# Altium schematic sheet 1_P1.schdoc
size 309 x 223 mm; Symbol: Sheet-Symbol_A4; Device: Sheet-Symbol_A4; Company: LuXeria; Drawed: Peanut; Reviewed: EasyEDA Pro; Version: V0.2; Page Size: A4; @Project Name: LuxBadge; @Page Count: 1; @Update Date: 2023-06-16; @Create Date: 2023-06-14; @Schematic Name: LuxBadge; Part Number: JLCPCB-002; @Page No: 1; @Page Name: P1
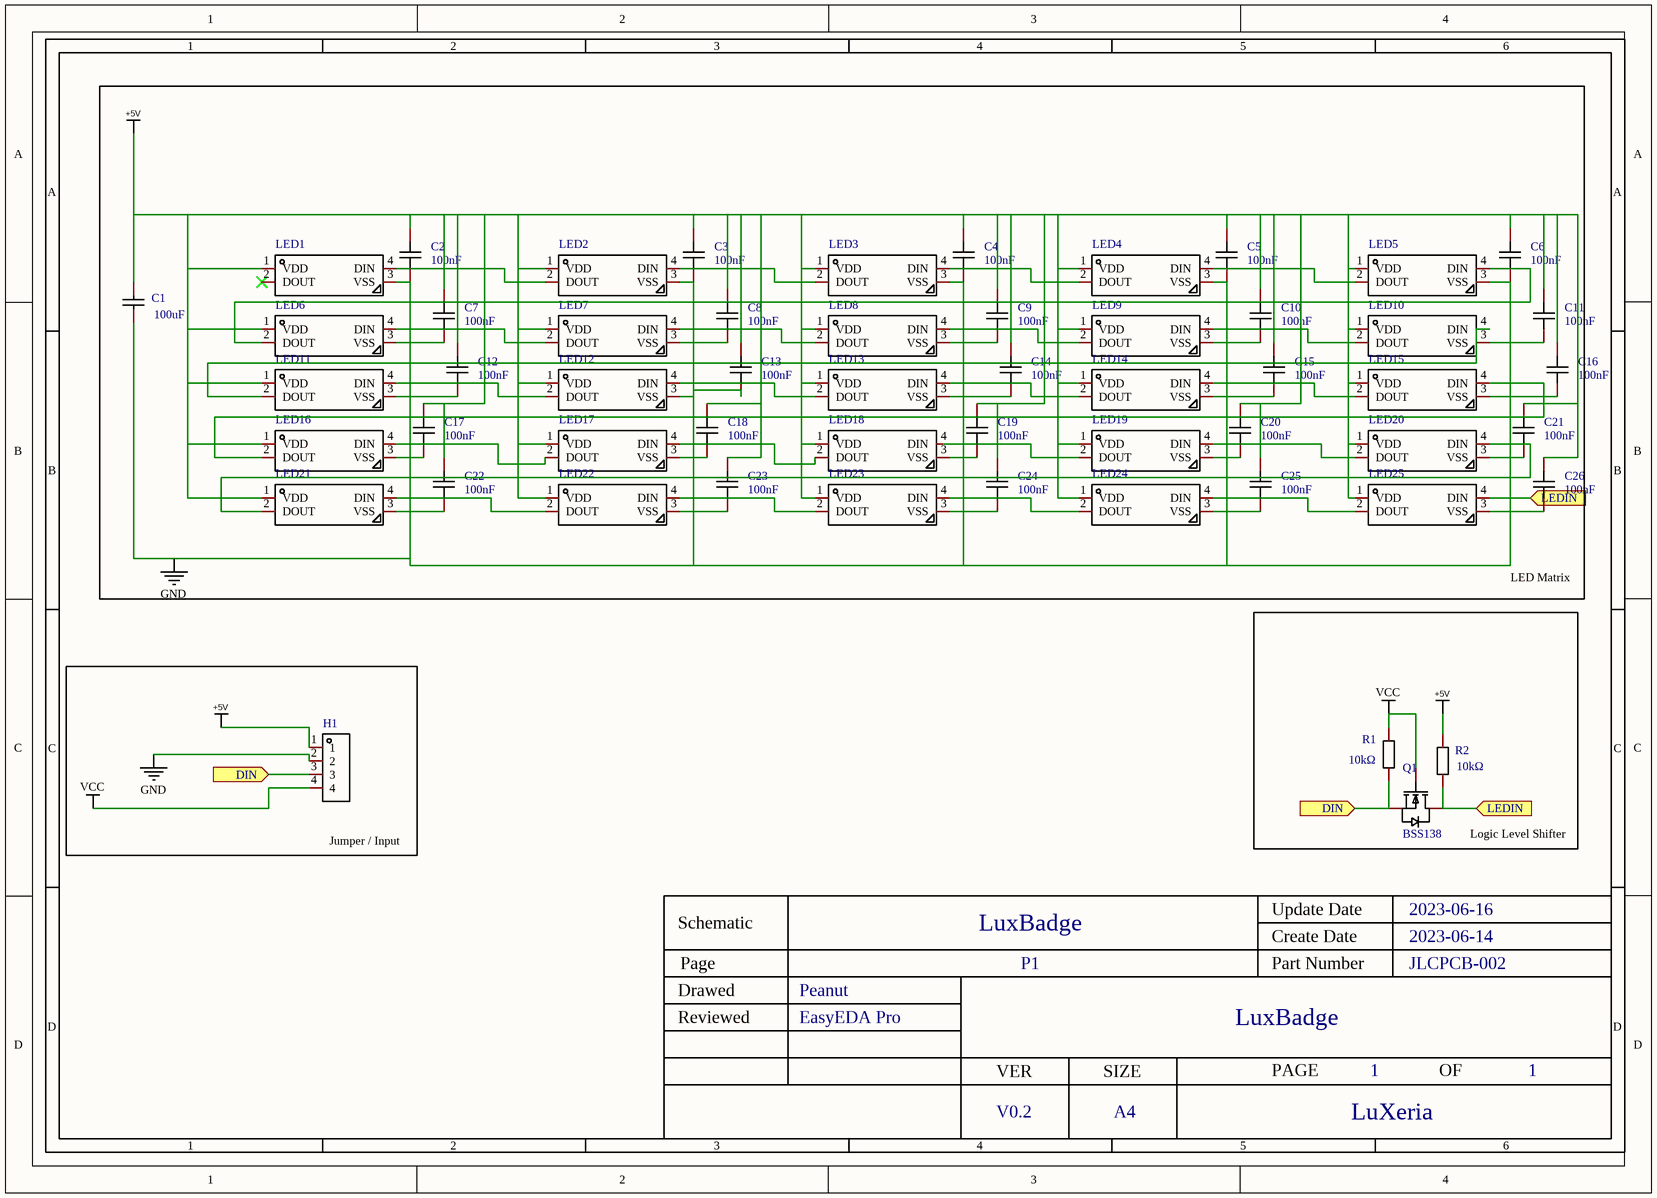
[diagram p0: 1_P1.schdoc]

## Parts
C1  100uF  [C1206]
C2  100nF  [C0402]
C3  100nF  [C0402]
C4  100nF  [C0402]
C5  100nF  [C0402]
C6  100nF  [C0402]
C7  100nF  [C0402]
C8  100nF  [C0402]
C9  100nF  [C0402]
C10  100nF  [C0402]
C11  100nF  [C0402]
C12  100nF  [C0402]
C13  100nF  [C0402]
C14  100nF  [C0402]
C15  100nF  [C0402]
C16  100nF  [C0402]
C17  100nF  [C0402]
C18  100nF  [C0402]
C19  100nF  [C0402]
C20  100nF  [C0402]
C21  100nF  [C0402]
C22  100nF  [C0402]
C23  100nF  [C0402]
C24  100nF  [C0402]
C25  100nF  [C0402]
C26  100nF  [C0402]
H1  2.54-1*4P母  [HDR-TH_4P-P2.54-V-F]  (value not drawn)
LED1  WS2812C/W  [LED-SMD_4P-L5.0-W5.0-TL_WS2812B-B]  (value not drawn)
LED2  WS2812C/W  [LED-SMD_4P-L5.0-W5.0-TL_WS2812B-B]  (value not drawn)
LED3  WS2812C/W  [LED-SMD_4P-L5.0-W5.0-TL_WS2812B-B]  (value not drawn)
LED4  WS2812C/W  [LED-SMD_4P-L5.0-W5.0-TL_WS2812B-B]  (value not drawn)
LED5  WS2812C/W  [LED-SMD_4P-L5.0-W5.0-TL_WS2812B-B]  (value not drawn)
LED6  WS2812C/W  [LED-SMD_4P-L5.0-W5.0-TL_WS2812B-B]  (value not drawn)
LED7  WS2812C/W  [LED-SMD_4P-L5.0-W5.0-TL_WS2812B-B]  (value not drawn)
LED8  WS2812C/W  [LED-SMD_4P-L5.0-W5.0-TL_WS2812B-B]  (value not drawn)
LED9  WS2812C/W  [LED-SMD_4P-L5.0-W5.0-TL_WS2812B-B]  (value not drawn)
LED10  WS2812C/W  [LED-SMD_4P-L5.0-W5.0-TL_WS2812B-B]  (value not drawn)
LED11  WS2812C/W  [LED-SMD_4P-L5.0-W5.0-TL_WS2812B-B]  (value not drawn)
LED12  WS2812C/W  [LED-SMD_4P-L5.0-W5.0-TL_WS2812B-B]  (value not drawn)
LED13  WS2812C/W  [LED-SMD_4P-L5.0-W5.0-TL_WS2812B-B]  (value not drawn)
LED14  WS2812C/W  [LED-SMD_4P-L5.0-W5.0-TL_WS2812B-B]  (value not drawn)
LED15  WS2812C/W  [LED-SMD_4P-L5.0-W5.0-TL_WS2812B-B]  (value not drawn)
LED16  WS2812C/W  [LED-SMD_4P-L5.0-W5.0-TL_WS2812B-B]  (value not drawn)
LED17  WS2812C/W  [LED-SMD_4P-L5.0-W5.0-TL_WS2812B-B]  (value not drawn)
LED18  WS2812C/W  [LED-SMD_4P-L5.0-W5.0-TL_WS2812B-B]  (value not drawn)
LED19  WS2812C/W  [LED-SMD_4P-L5.0-W5.0-TL_WS2812B-B]  (value not drawn)
LED20  WS2812C/W  [LED-SMD_4P-L5.0-W5.0-TL_WS2812B-B]  (value not drawn)
LED21  WS2812C/W  [LED-SMD_4P-L5.0-W5.0-TL_WS2812B-B]  (value not drawn)
LED22  WS2812C/W  [LED-SMD_4P-L5.0-W5.0-TL_WS2812B-B]  (value not drawn)
LED23  WS2812C/W  [LED-SMD_4P-L5.0-W5.0-TL_WS2812B-B]  (value not drawn)
LED24  WS2812C/W  [LED-SMD_4P-L5.0-W5.0-TL_WS2812B-B]  (value not drawn)
LED25  WS2812C/W  [LED-SMD_4P-L5.0-W5.0-TL_WS2812B-B]  (value not drawn)
Q1  BSS138  [SOT-23-3_L2.9-W1.3-P1.90-LS2.4-BR]
R1  10kΩ  [R0805]
R2  10kΩ  [R0805]

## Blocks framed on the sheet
LED Matrix: C1-C26 LED1-LED25
Logic Level Shifter: Q1 R1 R2
Jumper / Input: H1

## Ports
DIN (in), LEDIN (in)

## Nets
+5V: C1.2 C2.2 C3.2 C4.2 C5.2 C6.2 C7.2 C8.2 C9.2 C10.2 C11.2 C12.2 C13.2 C14.2 C15.2 C16.2 C17.2 C18.2 C19.2 C20.2 C21.2 C22.2 C23.2 C24.2 C25.2 C26.2 H1.1 LED1.1(VDD) LED2.1(VDD) LED3.1(VDD) LED4.1(VDD) LED5.1(VDD) LED6.1(VDD) LED7.1(VDD) LED8.1(VDD) LED9.1(VDD) LED10.1(VDD) LED11.1(VDD) LED12.1(VDD) LED13.1(VDD) LED14.1(VDD) LED15.1(VDD) LED16.1(VDD) LED17.1(VDD) LED18.1(VDD) LED19.1(VDD) LED20.1(VDD) LED21.1(VDD) LED22.1(VDD) LED23.1(VDD) LED24.1(VDD) LED25.1(VDD) R2.2
GND: C1.1 C2.1 C3.1 C4.1 C5.1 C6.1 C7.1 C8.1 C9.1 C10.1 C11.1 C12.1 C13.1 C14.1 C15.1 C16.1 C17.1 C18.1 C19.1 C20.1 C21.1 C22.1 C23.1 C24.1 C25.1 C26.1 H1.2 LED1.3(VSS) LED2.3(VSS) LED3.3(VSS) LED4.3(VSS) LED5.3(VSS) LED6.3(VSS) LED7.3(VSS) LED8.3(VSS) LED9.3(VSS) LED10.3(VSS) LED11.3(VSS) LED12.3(VSS) LED13.3(VSS) LED14.3(VSS) LED15.3(VSS) LED16.3(VSS) LED17.3(VSS) LED18.3(VSS) LED19.3(VSS) LED20.3(VSS) LED21.3(VSS) LED22.3(VSS) LED23.3(VSS) LED24.3(VSS) LED25.3(VSS)
VCC: H1.4 Q1.1(G) R1.2
DIN: H1.3 Q1.2(S) R1.1 ; port DIN
LEDIN: LED25.4(DIN) Q1.3(D) R2.1 ; port LEDIN
NetLED1_4: LED1.4(DIN) LED2.2(DOUT)
NetLED2_4: LED2.4(DIN) LED3.2(DOUT)
NetLED3_4: LED3.4(DIN) LED4.2(DOUT)
NetLED4_4: LED4.4(DIN) LED5.2(DOUT)
NetLED5_4: LED5.4(DIN) LED6.2(DOUT)
NetLED6_4: LED6.4(DIN) LED7.2(DOUT)
NetLED7_4: LED7.4(DIN) LED8.2(DOUT)
NetLED8_4: LED8.4(DIN) LED9.2(DOUT)
NetLED9_4: LED9.4(DIN) LED10.2(DOUT)
NetLED10_4: LED10.4(DIN) LED11.2(DOUT)
NetLED11_4: LED11.4(DIN) LED12.2(DOUT)
NetLED12_4: LED12.4(DIN) LED13.2(DOUT)
NetLED13_4: LED13.4(DIN) LED14.2(DOUT)
NetLED14_4: LED14.4(DIN) LED15.2(DOUT)
NetLED15_4: LED15.4(DIN) LED16.2(DOUT)
NetLED16_4: LED16.4(DIN) LED17.2(DOUT)
NetLED17_4: LED17.4(DIN) LED18.2(DOUT)
NetLED18_4: LED18.4(DIN) LED19.2(DOUT)
NetLED19_4: LED19.4(DIN) LED20.2(DOUT)
NetLED20_4: LED20.4(DIN) LED21.2(DOUT)
NetLED21_4: LED21.4(DIN) LED22.2(DOUT)
NetLED22_4: LED22.4(DIN) LED23.2(DOUT)
NetLED23_4: LED23.4(DIN) LED24.2(DOUT)
NetLED24_4: LED24.4(DIN) LED25.2(DOUT)

Not connected (* = marked no-connect by the designer): LED1 2(DOUT)*

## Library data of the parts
C1 = CL31A107MQHNNNE: Capacitance: Tolerance:±20% Tolerance:±20% Voltage Rated: Temperature Coefficient:; Manufacturer: SAMSUNG(三星); Add into BOM: yes; Tolerance: ±20%
C2-C26 = CC0402KRX7R5BB104: Capacitance: Tolerance:±10% Tolerance:±10% Voltage Rated: Temperature Coefficient:; Manufacturer: YAGEO(国巨); Add into BOM: yes; Tolerance: ±10%
H1 = 2.54-1*4P母: Number of Rows:单排 Number of Holes:4 Pitch:2.54mm Holes Structure:1x4P Row Spacing:- Mounting Type:Straight Circular Hole / Square Hole:Square Holes Current Rating (Max):3A Voltage Rating (Max):- Holes Direction:Top Insulation Height:- Contact Material:bro; Manufacturer: BOOMELE(博穆精密); Add into BOM: no; Convert to PCB: yes; Number of Holes: 4; Pitch: 2.54mm; Holes Structure: 1x4P; Current Rating (Max): 3A; Holes Direction: Top
LED1-LED25 = WS2812C/W: Emitted Color:RGB Diode Configuration:- Lens Color:- Dominant Wavelength:465nm~475nm；620nm~625nm；515nm~525nm Dominant Wavelength:465nm~475nm；620nm~625nm；515nm~525nm Peak Wavelength:- Color Temperature:- Color Temperature:- Forward Current:- Power Dissipat; Manufacturer: worldsemi; Add into BOM: yes; Emitted Color: RGB; Mounting Sytle: Positive post
Q1 = BSS138_C489349: Type: Drain Source Voltage (Vdss): Continuous Drain Current (Id): Power Dissipation (Pd): Drain Source On Resistance (RDS(on)@Vgs,Id):2.5Ω@10V,220mA Gate Threshold Voltage (Vgs(th)@Id):1.5V@250A; Manufacturer: KEXIN(科信); Add into BOM: yes
R1 R2 = 0805W8F1002T5E: Type:Thick Film Resistors Resistance: Tolerance:±1% Tolerance:±1% Power(Watts): Temperature Coefficient:±100ppm/℃ Temperature Coefficient:±100ppm/℃ Overload Voltage (Max): Operating Temperature Range:-55℃~+155℃ Operating Temperature Range:-55℃~+155℃; Manufacturer: UNI-ROYAL(厚声); Add into BOM: yes; Tolerance: ±1%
